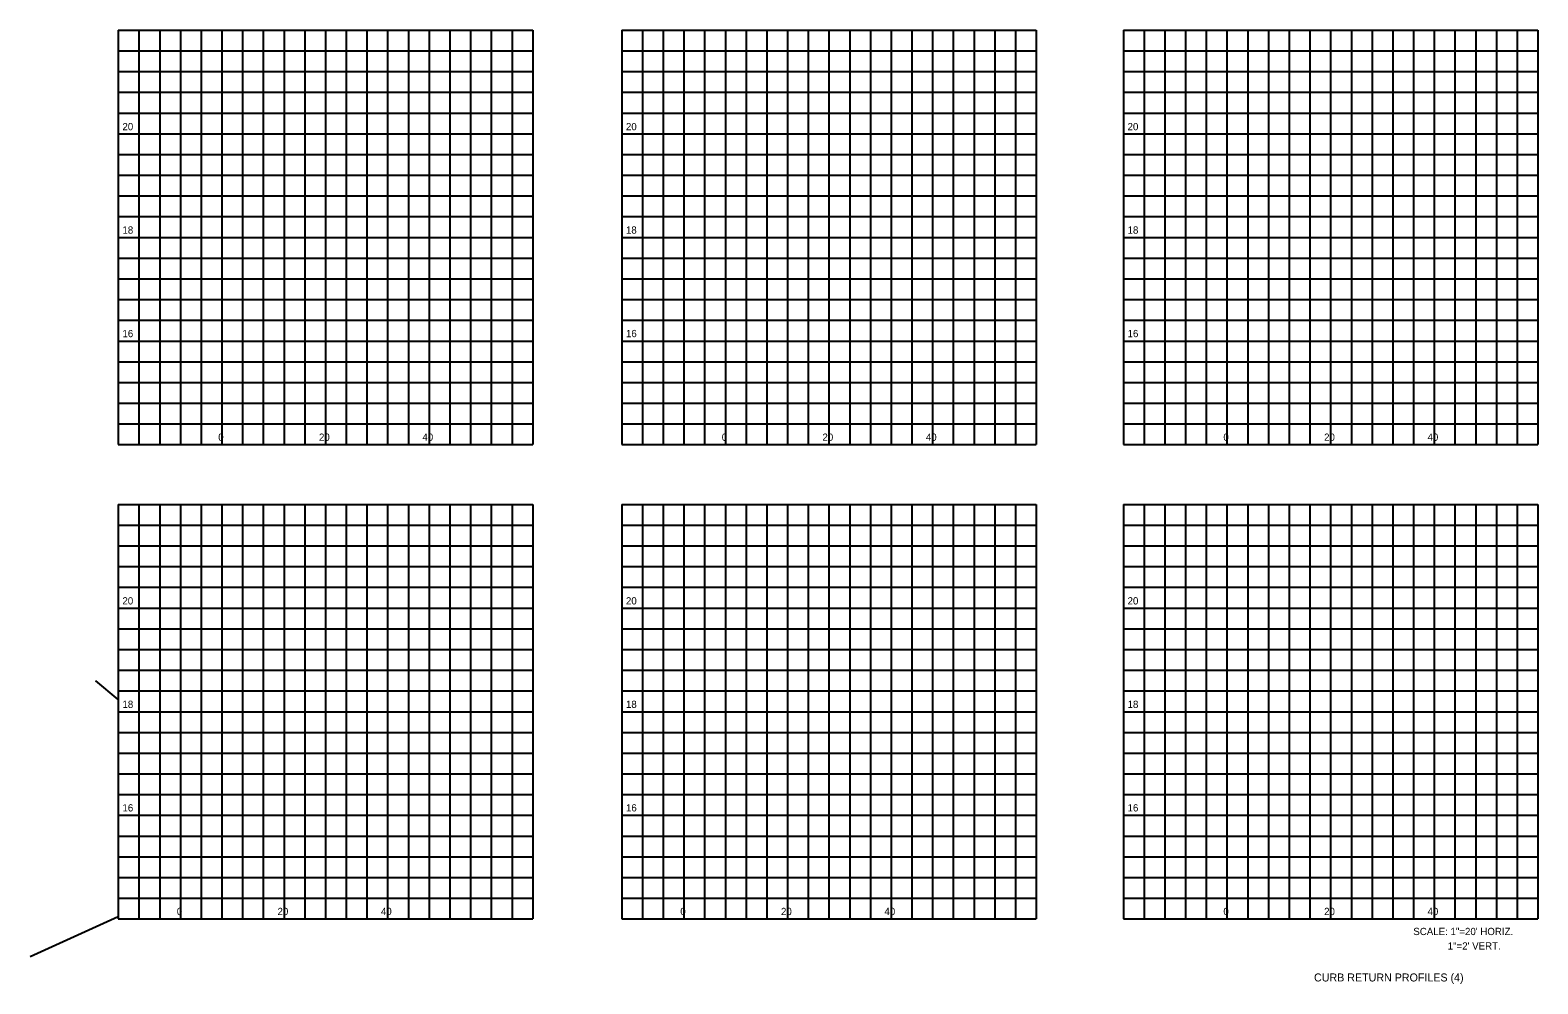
# Model space of a CAD drawing. Extents: x 127723 to 128378, y 21426 to 23736.
# Drawn here: x 127722.5 to 128013.5, y 22688.5 to 22872.6 of the extents above; entities that cross this region are included whole.
import ezdxf

# ---------------------------------------------------------------- set-up
doc = ezdxf.new("R2010")
doc.units = 0
for name, color, linetype in [('AdhocPoint_dp', 7, 'Continuous'), ('Default', 7, 'Continuous'), ('GroundCover', 7, 'Continuous'), ('Miscellaneous0', 7, 'Continuous'), ('SheetBorder_dp', 7, 'Continuous'), ('TextNotes', 7, 'Continuous')]:
    doc.layers.add(name, color=color, linetype=linetype)

msp = doc.modelspace()

# ---------------------------------------------------------------- linework, layer by layer
at = {"layer": 'AdhocPoint_dp'}
msp.add_lwpolyline([(127739.54, 22743.37), (127735.2, 22746.99), (127735.2, 22746.99)], dxfattribs=at)
at = {"layer": 'Miscellaneous0'}
for p, q in [((127743.54, 22872.59), (127743.54, 22792.59)), ((127747.54, 22872.59), (127747.54, 22792.59)), ((127751.54, 22872.59), (127751.54, 22792.59)), ((127755.54, 22872.59), (127755.54, 22792.59)), ((127763.54, 22872.59), (127763.54, 22792.59)), ((127767.54, 22872.59), (127767.54, 22792.59)), ((127771.54, 22872.59), (127771.54, 22792.59)), ((127775.54, 22872.59), (127775.54, 22792.59)), ((127783.54, 22872.59), (127783.54, 22792.59)), ((127787.54, 22872.59), (127787.54, 22792.59)), ((127791.54, 22872.59), (127791.54, 22792.59)), ((127795.54, 22872.59), (127795.54, 22792.59)), ((127803.54, 22872.59), (127803.54, 22792.59)), ((127807.54, 22872.59), (127807.54, 22792.59)), ((127811.54, 22872.59), (127811.54, 22792.59)), ((127815.54, 22872.59), (127815.54, 22792.59)), ((127840.72, 22872.59), (127840.72, 22792.59)), ((127844.72, 22872.59), (127844.72, 22792.59)), ((127848.72, 22872.59), (127848.72, 22792.59)), ((127852.72, 22872.59), (127852.72, 22792.59)), ((127860.72, 22872.59), (127860.72, 22792.59)), ((127864.72, 22872.59), (127864.72, 22792.59)), ((127868.72, 22872.59), (127868.72, 22792.59)), ((127872.72, 22872.59), (127872.72, 22792.59)), ((127880.72, 22872.59), (127880.72, 22792.59)), ((127884.72, 22872.59), (127884.72, 22792.59)), ((127888.72, 22872.59), (127888.72, 22792.59)), ((127892.72, 22872.59), (127892.72, 22792.59)), ((127900.72, 22872.59), (127900.72, 22792.59)), ((127904.72, 22872.59), (127904.72, 22792.59)), ((127908.72, 22872.59), (127908.72, 22792.59)), ((127912.72, 22872.59), (127912.72, 22792.59)), ((127937.54, 22872.59), (127937.54, 22792.59)), ((127941.54, 22872.59), (127941.54, 22792.59)), ((127945.54, 22872.59), (127945.54, 22792.59)), ((127949.54, 22872.59), (127949.54, 22792.59)), ((127957.54, 22872.59), (127957.54, 22792.59)), ((127961.54, 22872.59), (127961.54, 22792.59)), ((127965.54, 22872.59), (127965.54, 22792.59)), ((127969.54, 22872.59), (127969.54, 22792.59)), ((127977.54, 22872.59), (127977.54, 22792.59)), ((127981.54, 22872.59), (127981.54, 22792.59)), ((127985.54, 22872.59), (127985.54, 22792.59)), ((127989.54, 22872.59), (127989.54, 22792.59)), ((127997.54, 22872.59), (127997.54, 22792.59)), ((128001.54, 22872.59), (128001.54, 22792.59)), ((128005.54, 22872.59), (128005.54, 22792.59)), ((128009.54, 22872.59), (128009.54, 22792.59)), ((127739.54, 22868.59), (127819.54, 22868.59)), ((127836.72, 22868.59), (127916.72, 22868.59)), ((127933.54, 22868.59), (128013.54, 22868.59)), ((127739.54, 22864.59), (127819.54, 22864.59)), ((127836.72, 22864.59), (127916.72, 22864.59)), ((127933.54, 22864.59), (128013.54, 22864.59)), ((127739.54, 22860.59), (127819.54, 22860.59)), ((127836.72, 22860.59), (127916.72, 22860.59)), ((127933.54, 22860.59), (128013.54, 22860.59)), ((127739.54, 22856.59), (127819.54, 22856.59)), ((127836.72, 22856.59), (127916.72, 22856.59)), ((127933.54, 22856.59), (128013.54, 22856.59)), ((127739.54, 22848.59), (127819.54, 22848.59)), ((127836.72, 22848.59), (127916.72, 22848.59)), ((127933.54, 22848.59), (128013.54, 22848.59)), ((127739.54, 22844.59), (127819.54, 22844.59)), ((127836.72, 22844.59), (127916.72, 22844.59)), ((127933.54, 22844.59), (128013.54, 22844.59)), ((127739.54, 22840.59), (127819.54, 22840.59)), ((127836.72, 22840.59), (127916.72, 22840.59)), ((127933.54, 22840.59), (128013.54, 22840.59)), ((127739.54, 22836.59), (127819.54, 22836.59)), ((127836.72, 22836.59), (127916.72, 22836.59)), ((127933.54, 22836.59), (128013.54, 22836.59)), ((127739.54, 22828.59), (127819.54, 22828.59)), ((127836.72, 22828.59), (127916.72, 22828.59)), ((127933.54, 22828.59), (128013.54, 22828.59)), ((127739.54, 22824.59), (127819.54, 22824.59)), ((127836.72, 22824.59), (127916.72, 22824.59)), ((127933.54, 22824.59), (128013.54, 22824.59)), ((127739.54, 22820.59), (127819.54, 22820.59)), ((127836.72, 22820.59), (127916.72, 22820.59)), ((127933.54, 22820.59), (128013.54, 22820.59)), ((127739.54, 22816.59), (127819.54, 22816.59)), ((127836.72, 22816.59), (127916.72, 22816.59)), ((127933.54, 22816.59), (128013.54, 22816.59)), ((127739.54, 22808.59), (127819.54, 22808.59)), ((127836.72, 22808.59), (127916.72, 22808.59)), ((127933.54, 22808.59), (128013.54, 22808.59)), ((127739.54, 22804.59), (127819.54, 22804.59)), ((127836.72, 22804.59), (127916.72, 22804.59)), ((127933.54, 22804.59), (128013.54, 22804.59)), ((127739.54, 22800.59), (127819.54, 22800.59)), ((127836.72, 22800.59), (127916.72, 22800.59)), ((127933.54, 22800.59), (128013.54, 22800.59)), ((127739.54, 22796.59), (127819.54, 22796.59)), ((127836.72, 22796.59), (127916.72, 22796.59)), ((127933.54, 22796.59), (128013.54, 22796.59)), ((127743.54, 22781.05), (127743.54, 22701.05)), ((127747.54, 22781.05), (127747.54, 22701.05)), ((127755.54, 22781.05), (127755.54, 22701.05)), ((127759.54, 22781.05), (127759.54, 22701.05)), ((127763.54, 22781.05), (127763.54, 22701.05)), ((127767.54, 22781.05), (127767.54, 22701.05)), ((127775.54, 22781.05), (127775.54, 22701.05)), ((127779.54, 22781.05), (127779.54, 22701.05)), ((127783.54, 22781.05), (127783.54, 22701.05)), ((127787.54, 22781.05), (127787.54, 22701.05)), ((127795.54, 22781.05), (127795.54, 22701.05)), ((127799.54, 22781.05), (127799.54, 22701.05)), ((127803.54, 22781.05), (127803.54, 22701.05)), ((127807.54, 22781.05), (127807.54, 22701.05)), ((127811.54, 22781.05), (127811.54, 22701.05)), ((127815.54, 22781.05), (127815.54, 22701.05)), ((127840.72, 22781.05), (127840.72, 22701.05)), ((127844.72, 22781.05), (127844.72, 22701.05)), ((127852.72, 22781.05), (127852.72, 22701.05)), ((127856.72, 22781.05), (127856.72, 22701.05)), ((127860.72, 22781.05), (127860.72, 22701.05)), ((127864.72, 22781.05), (127864.72, 22701.05)), ((127872.72, 22781.05), (127872.72, 22701.05)), ((127876.72, 22781.05), (127876.72, 22701.05)), ((127880.72, 22781.05), (127880.72, 22701.05)), ((127884.72, 22781.05), (127884.72, 22701.05)), ((127892.72, 22781.05), (127892.72, 22701.05)), ((127900.72, 22781.05), (127900.72, 22701.05)), ((127904.72, 22781.05), (127904.72, 22701.05)), ((127908.72, 22781.05), (127908.72, 22701.05)), ((127912.72, 22781.05), (127912.72, 22701.05)), ((127937.54, 22781.05), (127937.54, 22701.05)), ((127941.54, 22781.05), (127941.54, 22701.05)), ((127945.54, 22781.05), (127945.54, 22701.05)), ((127949.54, 22781.05), (127949.54, 22701.05)), ((127957.54, 22781.05), (127957.54, 22701.05)), ((127961.54, 22781.05), (127961.54, 22701.05)), ((127965.54, 22781.05), (127965.54, 22701.05)), ((127969.54, 22781.05), (127969.54, 22701.05)), ((127977.54, 22781.05), (127977.54, 22701.05)), ((127981.54, 22781.05), (127981.54, 22701.05)), ((127985.54, 22781.05), (127985.54, 22701.05)), ((127989.54, 22781.05), (127989.54, 22701.05)), ((127997.54, 22781.05), (127997.54, 22701.05)), ((128001.54, 22781.05), (128001.54, 22701.05)), ((128005.54, 22781.05), (128005.54, 22701.05)), ((128009.54, 22781.05), (128009.54, 22701.05)), ((127739.54, 22777.05), (127819.54, 22777.05)), ((127836.72, 22777.05), (127916.72, 22777.05)), ((127933.54, 22777.05), (128013.54, 22777.05)), ((127739.54, 22773.05), (127819.54, 22773.05)), ((127836.72, 22773.05), (127916.72, 22773.05)), ((127933.54, 22773.05), (128013.54, 22773.05)), ((127739.54, 22769.05), (127819.54, 22769.05)), ((127836.72, 22769.05), (127916.72, 22769.05)), ((127933.54, 22769.05), (128013.54, 22769.05)), ((127739.54, 22765.05), (127819.54, 22765.05)), ((127836.72, 22765.05), (127916.72, 22765.05)), ((127933.54, 22765.05), (128013.54, 22765.05)), ((127739.54, 22757.05), (127819.54, 22757.05)), ((127836.72, 22757.05), (127916.72, 22757.05)), ((127933.54, 22757.05), (128013.54, 22757.05)), ((127739.54, 22753.05), (127819.54, 22753.05)), ((127836.72, 22753.05), (127916.72, 22753.05)), ((127933.54, 22753.05), (128013.54, 22753.05)), ((127739.54, 22749.05), (127819.54, 22749.05)), ((127836.72, 22749.05), (127916.72, 22749.05)), ((127933.54, 22749.05), (128013.54, 22749.05)), ((127739.54, 22745.05), (127819.54, 22745.05)), ((127836.72, 22745.05), (127916.72, 22745.05)), ((127933.54, 22745.05), (128013.54, 22745.05)), ((127739.54, 22737.05), (127819.54, 22737.05)), ((127836.72, 22737.05), (127916.72, 22737.05)), ((127933.54, 22737.05), (128013.54, 22737.05)), ((127739.54, 22733.05), (127819.54, 22733.05)), ((127836.72, 22733.05), (127916.72, 22733.05)), ((127933.54, 22733.05), (128013.54, 22733.05)), ((127739.54, 22729.05), (127819.54, 22729.05)), ((127836.72, 22729.05), (127916.72, 22729.05)), ((127933.54, 22729.05), (128013.54, 22729.05)), ((127739.54, 22725.05), (127819.54, 22725.05)), ((127836.72, 22725.05), (127916.72, 22725.05)), ((127933.54, 22725.05), (128013.54, 22725.05)), ((127739.54, 22717.05), (127819.54, 22717.05)), ((127836.72, 22717.05), (127916.72, 22717.05)), ((127933.54, 22717.05), (128013.54, 22717.05)), ((127739.54, 22713.05), (127819.54, 22713.05)), ((127836.72, 22713.05), (127916.72, 22713.05)), ((127933.54, 22713.05), (128013.54, 22713.05)), ((127739.54, 22709.05), (127819.54, 22709.05)), ((127836.72, 22709.05), (127916.72, 22709.05)), ((127933.54, 22709.05), (128013.54, 22709.05)), ((127739.54, 22705.05), (127819.54, 22705.05)), ((127836.72, 22705.05), (127916.72, 22705.05)), ((127933.54, 22705.05), (128013.54, 22705.05))]:
    msp.add_line(p, q, dxfattribs=at)
at = {"layer": 'SheetBorder_dp'}
for p, q in [((127739.54, 22872.59), (127819.54, 22872.59)), ((127739.54, 22872.59), (127739.54, 22792.59)), ((127759.54, 22872.59), (127759.54, 22812.59)), ((127759.54, 22872.59), (127759.54, 22792.59)), ((127779.54, 22872.59), (127779.54, 22792.59)), ((127799.54, 22872.59), (127799.54, 22792.59)), ((127819.54, 22872.59), (127819.54, 22792.59)), ((127836.72, 22872.59), (127916.72, 22872.59)), ((127836.72, 22872.59), (127836.72, 22792.59)), ((127856.72, 22872.59), (127856.72, 22812.59)), ((127856.72, 22872.59), (127856.72, 22792.59)), ((127876.72, 22872.59), (127876.72, 22792.59)), ((127896.72, 22872.59), (127896.72, 22792.59)), ((127916.72, 22872.59), (127916.72, 22792.59)), ((127933.54, 22872.59), (128013.54, 22872.59)), ((127933.54, 22872.59), (127933.54, 22792.59)), ((127953.54, 22872.59), (127953.54, 22812.59)), ((127953.54, 22872.59), (127953.54, 22792.59)), ((127973.54, 22872.59), (127973.54, 22792.59)), ((127993.54, 22872.59), (127993.54, 22792.59)), ((128013.54, 22872.59), (128013.54, 22792.59)), ((127739.54, 22852.59), (127819.54, 22852.59)), ((127836.72, 22852.59), (127916.72, 22852.59)), ((127933.54, 22852.59), (128013.54, 22852.59)), ((127739.54, 22832.59), (127819.54, 22832.59)), ((127836.72, 22832.59), (127916.72, 22832.59)), ((127933.54, 22832.59), (128013.54, 22832.59)), ((127739.54, 22812.59), (127819.54, 22812.59)), ((127739.54, 22812.59), (127819.54, 22812.59)), ((127836.72, 22812.59), (127916.72, 22812.59)), ((127836.72, 22812.59), (127916.72, 22812.59)), ((127933.54, 22812.59), (128013.54, 22812.59)), ((127933.54, 22812.59), (128013.54, 22812.59)), ((127739.54, 22792.59), (127819.54, 22792.59)), ((127836.72, 22792.59), (127916.72, 22792.59)), ((127933.54, 22792.59), (128013.54, 22792.59)), ((127739.54, 22781.05), (127819.54, 22781.05)), ((127739.54, 22781.05), (127739.54, 22701.05)), ((127751.54, 22781.05), (127751.54, 22701.05)), ((127759.54, 22781.05), (127759.54, 22721.05)), ((127771.54, 22781.05), (127771.54, 22701.05)), ((127791.54, 22781.05), (127791.54, 22701.05)), ((127819.54, 22781.05), (127819.54, 22701.05)), ((127836.72, 22781.05), (127916.72, 22781.05)), ((127836.72, 22781.05), (127836.72, 22701.05)), ((127848.72, 22781.05), (127848.72, 22701.05)), ((127856.72, 22781.05), (127856.72, 22721.05)), ((127868.72, 22781.05), (127868.72, 22701.05)), ((127888.72, 22781.05), (127888.72, 22701.05)), ((127896.72, 22781.05), (127896.72, 22701.05)), ((127916.72, 22781.05), (127916.72, 22701.05)), ((127933.54, 22781.05), (128013.54, 22781.05)), ((127933.54, 22781.05), (127933.54, 22701.05)), ((127953.54, 22781.05), (127953.54, 22721.05)), ((127953.54, 22781.05), (127953.54, 22701.05)), ((127973.54, 22781.05), (127973.54, 22701.05)), ((127993.54, 22781.05), (127993.54, 22701.05)), ((128013.54, 22781.05), (128013.54, 22701.05)), ((127739.54, 22761.05), (127819.54, 22761.05)), ((127836.72, 22761.05), (127916.72, 22761.05)), ((127933.54, 22761.05), (128013.54, 22761.05)), ((127739.54, 22741.05), (127819.54, 22741.05)), ((127836.72, 22741.05), (127916.72, 22741.05)), ((127933.54, 22741.05), (128013.54, 22741.05)), ((127739.54, 22721.05), (127819.54, 22721.05)), ((127739.54, 22721.05), (127819.54, 22721.05)), ((127836.72, 22721.05), (127916.72, 22721.05)), ((127836.72, 22721.05), (127916.72, 22721.05)), ((127933.54, 22721.05), (128013.54, 22721.05)), ((127933.54, 22721.05), (128013.54, 22721.05)), ((127739.54, 22701.05), (127819.54, 22701.05)), ((127836.72, 22701.05), (127916.72, 22701.05)), ((127933.54, 22701.05), (128013.54, 22701.05))]:
    msp.add_line(p, q, dxfattribs=at)
at = {"layer": 'TextNotes'}
msp.add_line((127739.54, 22701.43), (127722.54, 22693.76), dxfattribs=at)

# ---------------------------------------------------------------- texts
at = {"layer": 'Default'}
msp.add_text('CURB RETURN PROFILES (4)', height=1.5418, dxfattribs=at).set_placement((127970.34, 22688.98))
at = {"layer": 'GroundCover'}
for s, p in [('20', (127740.35, 22853.27)), ('20', (127837.53, 22853.27)), ('20', (127934.35, 22853.27)), ('18', (127740.35, 22833.31)), ('18', (127837.53, 22833.31)), ('18', (127934.35, 22833.31)), ('16', (127740.35, 22813.33)), ('16', (127837.53, 22813.33)), ('16', (127934.35, 22813.33)), ('0', (127758.84, 22793.33)), ('20', (127778.28, 22793.33)), ('40', (127798.24, 22793.33)), ('0', (127856.02, 22793.33)), ('20', (127875.46, 22793.33)), ('40', (127895.42, 22793.33)), ('0', (127952.84, 22793.33)), ('20', (127972.28, 22793.33)), ('40', (127992.24, 22793.33)), ('20', (127740.35, 22761.74)), ('20', (127837.53, 22761.74)), ('20', (127934.35, 22761.74)), ('18', (127740.35, 22741.77)), ('18', (127837.53, 22741.77)), ('18', (127934.35, 22741.77)), ('16', (127740.35, 22721.79)), ('16', (127837.53, 22721.79)), ('16', (127934.35, 22721.79)), ('0', (127750.85, 22701.79)), ('20', (127770.28, 22701.79)), ('40', (127790.24, 22701.79)), ('0', (127848.02, 22701.79)), ('20', (127867.46, 22701.79)), ('40', (127887.42, 22701.79)), ('0', (127952.84, 22701.79)), ('20', (127972.28, 22701.79)), ('40', (127992.24, 22701.79)), ('SCALE: 1"=20\' HORIZ.', (127989.5, 22697.93)), ('  1"=2\' VERT.', (127995.1, 22695.13))]:
    msp.add_text(s, height=1.4, dxfattribs=at).set_placement(p)

doc.saveas('drawing.dxf')
